// Mitsubishi GX Works2 project: MM-20MR-4MTS-450LED-FX-B L   PLC: FX1S

PROGRAM MAIN
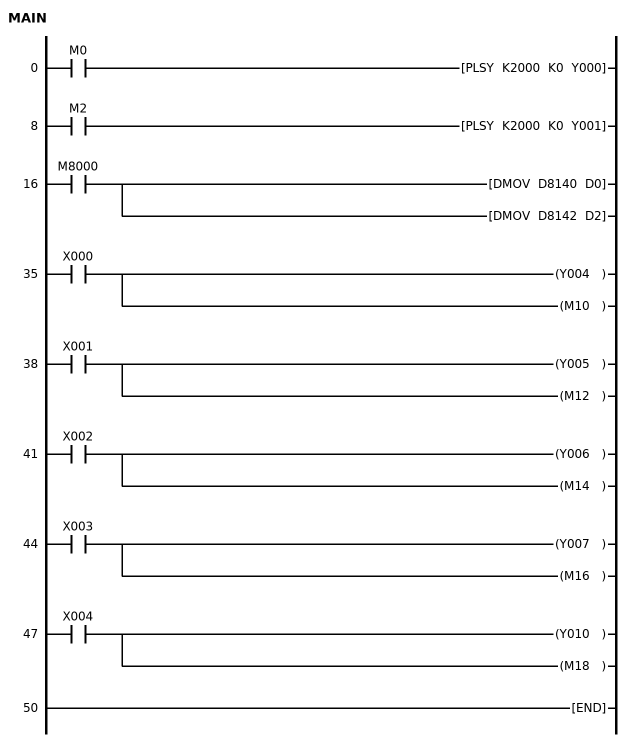
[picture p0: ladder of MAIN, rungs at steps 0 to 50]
0     LD      M0
      PLSY    K2000 K0 Y000
8     LD      M2
      PLSY    K2000 K0 Y001
16    LD      M8000
      DMOV    D8140 D0
      DMOV    D8142 D2
35    LD      X000
      OUT     Y004
      OUT     M10
38    LD      X001
      OUT     Y005
      OUT     M12
41    LD      X002
      OUT     Y006
      OUT     M14
44    LD      X003
      OUT     Y007
      OUT     M16
47    LD      X004
      OUT     Y010
      OUT     M18
50    END
END_PROGRAM
